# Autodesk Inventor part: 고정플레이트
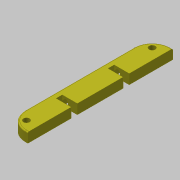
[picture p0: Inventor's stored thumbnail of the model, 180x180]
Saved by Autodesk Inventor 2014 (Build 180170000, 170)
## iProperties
Created: 2018-08
Part Number: 고정플레이트
Material: ABS 플라스틱
Document SubType Name: Modeling
Designer: mduedu
Density: 1.06 g/cm^3
Appearance: Canary
Mass: 13.199 g
Surface Area: 67.9758 cm^2
Volume: 12.4519 cm^3
Author: mduedu
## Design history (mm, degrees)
sketch "스케치1"
  geometry: L1 (0, -60)-(17, -60); L2 (17, -60)-(17, 60); L3 (17, 60)-(0, 60); L4 (0, 60)-(0, -60); 2 further points
  constraints: 8 end point, 2 parallel, 1 coincident, 1 horizontal, 1 midpoint, 1 perpendicular
  dimensions: "d0" = 120 distance between parallel lines of L3 L1; "d2" = 17 distance of L1.start L1.end
extrude "돌출1" new body sketch "스케치1" distance "d3" = 8; taper "d4" = 0 deg
fillet "모깎기1" dims "d5" = 15
fillet "모깎기2" dims "d6" = 1
sketch "스케치2"
  geometry: L1 (-17, 0)-(-17, 7) reference; L2 (0, 0)-(-17, 0) reference; L3 (-12.5, 4)-(-12.5, 0); L4 (-7.5, 4)-(-7.5, 0); A1 r 2.5 centre (-10, 4) between (-12.5, 4) and (-7.5, 4)
  constraints: 4 end point, 2 perpendicular, 2 point on circle, 2 point on line, 2 tangent, 1 centre point
  dimensions: "d7" = 5 diameter of A1; "d8" = 7 distance from line of A1.centre L1; "d9" = 4 distance from line of L2 A1.centre
extrude "돌출2" cut sketch "스케치2" stored distance "d10" = 70; taper "d11" = 0 deg
fillet "모깎기3" dims "d12" = 2.5
sketch "스케치3"
  geometry: L1 (-12.5, -19)-(0, -19); L2 (0, -19)-(0, -24); L3 (0, -24)-(-12.5, -24); L4 (-12.5, -24)-(-12.5, -19); L5 (0, -59)-(0, 59) reference; L6 (-17, 45)-(-17, -45) reference; 2 further points
  constraints: 8 end point, 2 parallel, 1 horizontal, 1 midpoint, 1 perpendicular, 1 vertical alignment
  dimensions: "d13" = 4.5 distance between parallel lines of L4 L6; "d14" = 19 distance from line of L1 point (0, 0); "d15" = 5 distance of L1.end L2.end
extrude "돌출3" cut sketch "스케치3" stored distance "d16" = 70; taper "d17" = 0 deg
sketch "스케치4"
  geometry: A1 r 15 centre (-2, -45) between (-17, -45) and (-2, -60) reference; A2 r 15 centre (-2, 45) between (-2, 60) and (-17, 45) reference; A3 r 10 centre (-2, 45) between (-2, 55) and (-12, 45); A4 r 10 centre (-2, -45) between (-12, -45) and (-2, -55); 3 further points
  constraints: 6 point on circle, 2 centre point, 2 horizontal alignment, 2 vertical alignment
  dimensions: "d18" = 5 radial gap between concentric circles of A3 A2; "d19" = 5 radial gap between concentric circles of A1 A4
hole "구멍1" sketch "스케치4" at (-9.071, 52.071), (-9.071, -52.071) diameter "d20" = 5; stored, may be unused: countersink angle "d24" = 90 deg, drill point angle "d26" = 118 deg; dims "d21" = 6, "d22" = 4, "d23" = 2, "d25" = 8
node "솔리드1"
mirror "대칭1"
